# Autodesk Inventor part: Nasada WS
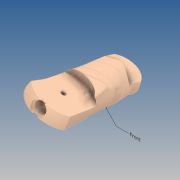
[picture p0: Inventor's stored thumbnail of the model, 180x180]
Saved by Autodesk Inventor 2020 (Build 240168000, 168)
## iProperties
Created: 2019-10
Part Number: Nasada WS
Material: GFRP
Document SubType Name: Modeling
Designer: yello
Density: 1.75 g/cm^3
Appearance: Default
Author: yello
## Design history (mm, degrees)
node "Annotations"
  node "Leader Text 1"
feature "Nasada WS"
workplane "Work Plane1"
sketch "Sketch2"
  geometry: L1 (3.5, 0)-(3.5, 20); L2 (3.5, 20)-(-3.5, 20); L3 (-3.5, 20)-(-3.5, 0); L4 (-3.5, 0)-(-3.5, -30); L5 (-3.5, -30)-(3.5, -30); L6 (3.5, -30)-(3.5, 0); L7 (0, -30)-(0, 20); A1 r 3.5 centre (0, 0) between (3.5, 0) and (-3.5, 0)
  constraints: 14 end point, 3 perpendicular, 2 midpoint, 2 point on circle, 2 point on line, 2 tangent, 1 centre point, 1 vertical
  dimensions: "d2" = 7 diameter of A1; "d3" = 20 distance of L1.start L1.end; "d4" = 30 distance of L3.end L4.end
revolve "Revolution1" sketch "Sketch2" stored, may be unused: angle "d5" = 90 deg
workplane "Work Plane3"
sketch "Sketch10"
  geometry: C1 r 95.129 at (-22.981, -21.642); 1 further point
  constraints: 1 centre point
workplane "Work Plane5"
sketch "Sketch14"
  geometry: C1 r 4.25 at (0, 0); A1 r 3.5 centre (0, 0) between (3.274, -1.237) and (3.274, -1.237) reference
  constraints: 1 centre point, 1 coincident
  dimensions: "d16" = 8.5 diameter of C1
extrude "Extrusion4" cut sketch "Sketch14" stored distance "d17" = 2; taper "d18" = 0 deg
workplane "Work Plane6"
sketch "Sketch15"
  geometry: L1 (0, 1.5)-(0, -1.5); A1 r 1.5 centre (0, 0) between (0, 1.5) and (0, -1.5); 1 further point
  constraints: 2 end point, 2 point on circle, 1 centre point, 1 vertical
  dimensions: "d21" = 3 diameter of A1
revolve "Revolution2" sketch "Sketch15" stored, may be unused: angle "d22" = 90 deg
mirror "Mirror1"
workaxis "Work Axis1"
body "Solid1"
other parameters: "d15" = 45, "d19" = 3.5, "d0" = 5.52823 (derived), "d1" = 5.43574 (derived)
